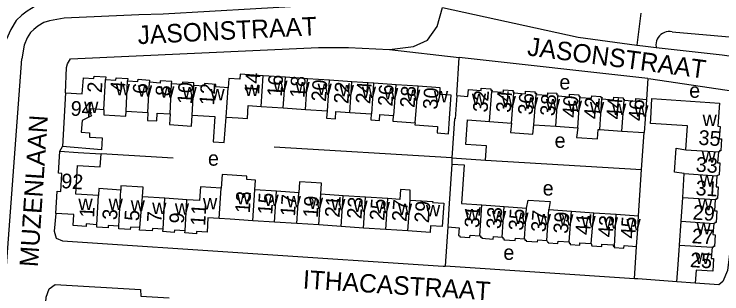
# Model space of a CAD drawing. Extents: x 161773 to 163836, y 384796 to 386521.
# Drawn here: x 162054.9 to 162246.8, y 386283.2 to 386359.1 of the extents above; entities that cross this region are included whole.
import ezdxf

# ---------------------------------------------------------------- set-up
doc = ezdxf.new("R2010")
doc.units = 0
for name, color, linetype in [('BLT_Basislijn', 7, 'Continuous'), ('BLT_Bebouwing', 7, 'Continuous'), ('BLT_Centroide', 7, 'Continuous'), ('BLT_Huisnummer', 7, 'Continuous'), ('BLT_Huisnummer_ tussenligend', 7, 'Continuous'), ('BLT_Huisnummer_reeks', 7, 'Continuous'), ('BLT_Onderverdeling_panden', 7, 'Continuous'), ('BLT_Straatnaam', 7, 'Continuous')]:
    doc.layers.add(name, color=color, linetype=linetype)

msp = doc.modelspace()

# ---------------------------------------------------------------- linework, layer by layer
at = {"layer": 'BLT_Basislijn'}
for p, q in [((162224.77, 386359.37), (162223.74, 386350.72)), ((162088.68, 386358.9), (162068.41, 386357.99)), ((162156.67, 386349.55), (162175.59, 386347.38)), ((162047.33, 386216.15), (162056.95, 386346.98)), ((162174.88, 386337.01), (162175.59, 386347.38)), ((162226.68, 386341.63), (162175.59, 386347.38)), ((162226.68, 386341.63), (162226.35, 386335.99)), ((162225.02, 386316.96), (162225.69, 386326.97)), ((162173.52, 386320.1), (162125.43, 386323.03)), ((162097.96, 386320.09), (162078.46, 386321.21)), ((162173.52, 386320.1), (162173.54, 386318.44)), ((162182.71, 386319.47), (162225.02, 386316.96)), ((162224.19, 386304.39), (162225.02, 386316.96)), ((162172.45, 386301.39), (162171.77, 386290.74)), ((162223.06, 386287.36), (162223.66, 386296.1)), ((162223.06, 386287.36), (162171.77, 386290.74))]:
    msp.add_line(p, q, dxfattribs=at)
for points in [[(162067.88, 386362.97), (162063.25, 386362.18), (162060.78, 386361.41), (162058.37, 386359.89), (162056.99, 386358.79), (162055.44, 386357.35), (162053.96, 386354.94), (162052.75, 386352.1), (162052.68, 386351.64)], [(162132.96, 386361.27), (162095.26, 386359.13), (162088.68, 386358.9)], [(162156.67, 386349.55), (162163.16, 386350.3), (162166.96, 386352.02), (162169.55, 386355.75), (162171.05, 386360.94)], [(162171.05, 386360.94), (162207.82, 386352.89), (162223.74, 386350.72)], [(162068.41, 386357.99), (162064.42, 386357.31), (162062.89, 386356.83), (162061.27, 386355.81), (162060.25, 386354.99), (162059.34, 386354.15), (162058.42, 386352.65), (162057.59, 386350.68), (162056.95, 386346.98)], [(162233.3, 386354.28), (162232.77, 386354.36), (162232.23, 386354.36), (162231.7, 386354.29), (162231.19, 386354.13), (162230.7, 386353.9), (162230.26, 386353.6), (162229.86, 386353.23), (162229.53, 386352.82), (162229.26, 386352.35), (162229.06, 386351.85), (162228.93, 386351.33), (162228.89, 386350.8), (162228.93, 386350.26), (162228.95, 386350.1)], [(162233.3, 386354.28), (162265.36, 386351.49), (162269.14, 386352.49), (162269.74, 386352.29), (162268.92, 386345.92)], [(162068.81, 386337.78), (162069.09, 386344.65), (162069.34, 386345.65), (162070.13, 386346.96), (162137.43, 386350.02), (162145.51, 386350.06), (162156.67, 386349.55)], [(162223.74, 386350.72), (162225.34, 386350.5), (162228.95, 386350.1)], [(162228.95, 386350.1), (162246.84, 386348.11), (162257.79, 386346.51)], [(162226.68, 386341.63), (162227.56, 386341.53), (162250.01, 386338.22), (162251.35, 386337.36), (162252.67, 386335.96), (162253.5, 386333.29), (162253.45, 386331.89), (162248.27, 386289.55), (162247.01, 386286.61), (162245.96, 386285.7), (162239.56, 386286.16)], [(162067.26, 386321.95), (162068.01, 386323.2)], [(162066.15, 386305.08), (162065.72, 386300.28), (162066.31, 386298.33), (162067.96, 386297.64), (162171.21, 386290.78), (162171.77, 386290.74)], [(162234.62, 386286.49), (162224.01, 386287.3), (162223.06, 386287.36)], [(162060.34, 386233.61), (162060.37, 386234.09), (162063.55, 386282.31), (162064.37, 386284.59), (162065.99, 386285.78), (162089.17, 386284.41), (162089.19, 386282.64), (162096.88, 386282.13)]]:
    msp.add_lwpolyline(points, dxfattribs=at)
at = {"layer": 'BLT_Bebouwing'}
for p, q in [((162128.44, 386341.98), (162122.44, 386342.38)), ((162134.43, 386341.57), (162128.44, 386341.98)), ((162079.65, 386341.41), (162079.66, 386341.41)), ((162140.43, 386341.16), (162134.43, 386341.57)), ((162146.43, 386340.75), (162140.43, 386341.16)), ((162152.43, 386340.35), (162146.43, 386340.75)), ((162158.43, 386339.94), (162152.43, 386340.35)), ((162112.89, 386339.12), (162109.55, 386339.35)), ((162164.43, 386339.53), (162158.43, 386339.94)), ((162068.81, 386337.78), (162068.01, 386323.2)), ((162068.81, 386337.78), (162073.36, 386337.47)), ((162085.24, 386332.79), (162091.15, 386332.43)), ((162121.87, 386334.08), (162127.87, 386333.67)), ((162127.87, 386333.67), (162133.87, 386333.27)), ((162133.87, 386333.27), (162139.75, 386332.87)), ((162145.87, 386332.45), (162151.68, 386332.05)), ((162183.79, 386329.97), (162189.77, 386329.54)), ((162195.76, 386329.11), (162201.74, 386328.69)), ((162201.74, 386328.69), (162207.73, 386328.26)), ((162213.72, 386327.83), (162219.7, 386327.4)), ((162219.7, 386327.4), (162225.69, 386326.97)), ((162078.53, 386322.33), (162068.01, 386323.2)), ((162173.52, 386320.1), (162182.71, 386319.47)), ((162236.17, 386309.4), (162236.6, 386315.87)), ((162126.04, 386311.08), (162120.14, 386311.47)), ((162095.7, 386309.17), (162089.72, 386309.57)), ((162132.07, 386310.68), (162126.04, 386311.08)), ((162144.13, 386309.87), (162138.03, 386310.28)), ((162150.16, 386309.47), (162144.13, 386309.87)), ((162156.2, 386309.07), (162150.16, 386309.47)), ((162235.73, 386302.93), (162236.17, 386309.4)), ((162101.69, 386308.77), (162095.7, 386309.17)), ((162181.7, 386307.38), (162187.77, 386306.95)), ((162187.77, 386306.95), (162193.84, 386306.52)), ((162199.91, 386306.1), (162205.98, 386305.67)), ((162205.98, 386305.67), (162212.05, 386305.24)), ((162212.05, 386305.24), (162218.12, 386304.82)), ((162218.12, 386304.82), (162224.19, 386304.39)), ((162125.49, 386302.69), (162119.59, 386303.07)), ((162131.52, 386302.29), (162125.49, 386302.69)), ((162137.48, 386301.93), (162131.52, 386302.29)), ((162143.58, 386301.49), (162137.48, 386301.93)), ((162235.29, 386296.46), (162235.73, 386302.93)), ((162088.91, 386300.52), (162088.95, 386301.2)), ((162149.61, 386301.09), (162143.58, 386301.49)), ((162155.64, 386300.69), (162149.61, 386301.09)), ((162161.67, 386300.29), (162155.64, 386300.69))]:
    msp.add_line(p, q, dxfattribs=at)
for points in [[(162073.36, 386337.47), (162073.65, 386341.86), (162076.53, 386341.67), (162076.58, 386342.29), (162079.7, 386342.08), (162079.65, 386341.41)], [(162122.44, 386342.38), (162116.14, 386342.81), (162116.05, 386341.44), (162113.06, 386341.64), (162112.89, 386339.12)], [(162079.66, 386341.41), (162082.45, 386341.22), (162082.5, 386341.85), (162085.66, 386341.63), (162085.62, 386341)], [(162085.62, 386341), (162088.46, 386340.81), (162088.51, 386341.45), (162091.59, 386341.24), (162091.54, 386340.63)], [(162097.55, 386340.2), (162097.6, 386340.84), (162094.49, 386341.05), (162094.45, 386340.43), (162091.54, 386340.63)], [(162103.59, 386339.76), (162103.64, 386340.45), (162100.49, 386340.67), (162100.45, 386340), (162097.55, 386340.2)], [(162109.55, 386339.35), (162109.6, 386340.06), (162106.49, 386340.27), (162106.44, 386339.57), (162103.59, 386339.76)], [(162173.4, 386337.1), (162170.27, 386337.32), (162170.4, 386339.13), (162164.43, 386339.53)], [(162174.88, 386337.01), (162177.93, 386336.8), (162178.05, 386338.64), (162181.51, 386338.4), (162181.55, 386339.03), (162184.17, 386338.85), (162184.14, 386338.47), (162184.47, 386338.45), (162184.37, 386338.14)], [(162184.37, 386338.14), (162187.53, 386337.92), (162187.58, 386338.61), (162190.15, 386338.43), (162190.12, 386338.05), (162190.4, 386338.04), (162190.38, 386337.75)], [(162190.38, 386337.75), (162193.53, 386337.53), (162193.58, 386338.2), (162196.12, 386338.02), (162196.1, 386337.66), (162196.48, 386337.64), (162196.46, 386337.33)], [(162163.58, 386329.65), (162163.54, 386329.06), (162169.7, 386328.6), (162169.57, 386326.9), (162172.69, 386326.67), (162172.97, 386330.81), (162173.06, 386332.12), (162173.4, 386337.1)], [(162174.88, 386337.01), (162174.54, 386332.02), (162174.45, 386330.71), (162174.25, 386330.72), (162173.52, 386320.1)], [(162196.46, 386337.33), (162199.55, 386337.12), (162199.59, 386337.76), (162202, 386337.64), (162201.97, 386337.28), (162202.34, 386337.25), (162202.33, 386336.93)], [(162202.33, 386336.93), (162205.43, 386336.7), (162205.48, 386337.39), (162207.99, 386337.21), (162207.97, 386336.86), (162208.29, 386336.83), (162208.27, 386336.53)], [(162208.27, 386336.53), (162211.44, 386336.29), (162211.5, 386336.99), (162214.01, 386336.81), (162213.98, 386336.48), (162214.31, 386336.46), (162214.28, 386336.14)], [(162214.28, 386336.14), (162217.42, 386335.91), (162217.47, 386336.61), (162220.04, 386336.43), (162220.01, 386336.07), (162220.29, 386336.05), (162220.3, 386335.74)], [(162220.3, 386335.74), (162223.43, 386335.51), (162223.48, 386336.2), (162226.35, 386335.99)], [(162237.04, 386322.34), (162237.47, 386328.82), (162227.47, 386329.49), (162227.55, 386330.75), (162227.83, 386336.23), (162246.14, 386335), (162245.65, 386328.72), (162246.31, 386328.67), (162246.08, 386325.3), (162246.73, 386325.25), (162246.51, 386322.07), (162246.15, 386322.09), (162246.13, 386321.8), (162245.83, 386321.75)], [(162118.13, 386330.81), (162118.34, 386334.32), (162121.87, 386334.08)], [(162226.35, 386335.99), (162225.96, 386330.64), (162225.69, 386326.97)], [(162075.59, 386333.4), (162075.52, 386332.26), (162075.87, 386331.51), (162073.28, 386330.28), (162073.04, 386327.07), (162075.35, 386326.9), (162075.27, 386325.78), (162078.76, 386325.53), (162078.53, 386322.33)], [(162079.17, 386333.16), (162078.08, 386333.22), (162075.59, 386333.4)], [(162079.17, 386333.16), (162079.16, 386331.77), (162085.13, 386331.41), (162085.24, 386332.79)], [(162091.15, 386332.43), (162091.01, 386330.3), (162093.53, 386330.16), (162093.65, 386332.28), (162097.15, 386332.07)], [(162139.75, 386332.87), (162139.62, 386330.88), (162141.99, 386330.72), (162142.12, 386332.7), (162145.87, 386332.45)], [(162097.15, 386332.07), (162096.96, 386329.18), (162102.99, 386328.77), (162103.19, 386331.71)], [(162103.19, 386331.71), (162109.29, 386331.34), (162108.81, 386324.46), (162111.85, 386324.25), (162112.33, 386331.16)], [(162112.33, 386331.16), (162115.63, 386330.96), (162118.13, 386330.81)], [(162151.68, 386332.05), (162151.57, 386330.42), (162153.94, 386330.26), (162154.05, 386331.89), (162157.69, 386331.65)], [(162157.69, 386331.65), (162157.57, 386330.06), (162163.58, 386329.65)], [(162182.71, 386319.47), (162182.98, 386323.38), (162177.35, 386323.77), (162177.8, 386330.4), (162183.79, 386329.97)], [(162189.77, 386329.54), (162189.51, 386326.99), (162195.54, 386326.58), (162195.76, 386329.11)], [(162207.73, 386328.26), (162207.38, 386325.67), (162213.09, 386325.28), (162213.26, 386327.86), (162213.72, 386327.83)], [(162066.15, 386305.08), (162066.55, 386311.11), (162067.52, 386311.04), (162067.84, 386315.92), (162066.86, 386315.99), (162067.26, 386321.95)], [(162067.26, 386321.95), (162072.25, 386321.62), (162078.46, 386321.21)], [(162077.71, 386309.91), (162071.56, 386310.32), (162072.08, 386318.07), (162078.22, 386317.66), (162078.46, 386321.21)], [(162236.6, 386315.87), (162233.97, 386316.23), (162234.41, 386322.73), (162237.04, 386322.34)], [(162245.83, 386321.75), (162245.63, 386318.82), (162246.26, 386318.78), (162246.04, 386315.52), (162245.43, 386315.28)], [(162173.54, 386318.44), (162172.77, 386306.38), (162172.45, 386301.39)], [(162173.54, 386318.44), (162176.88, 386318.23), (162176.21, 386307.76), (162181.7, 386307.38)], [(162120.14, 386311.47), (162120.31, 386314.07), (162117.94, 386314.23), (162118, 386315.12), (162111.24, 386315.57), (162110.98, 386311.92)], [(162245.43, 386315.28), (162245.23, 386312.3), (162245.82, 386312.26), (162245.61, 386309.08), (162245.3, 386309.1), (162245.29, 386308.85), (162244.97, 386308.81)], [(162138.03, 386310.28), (162138.22, 386313.27), (162135.46, 386313.46), (162132.29, 386313.67), (162132.07, 386310.68)], [(162083.78, 386311.41), (162077.84, 386311.8), (162077.71, 386309.91)], [(162089.72, 386309.57), (162089.83, 386312.16), (162083.81, 386312.57), (162083.78, 386311.41)], [(162110.98, 386311.92), (162105.39, 386312.29), (162105.14, 386308.54), (162101.69, 386308.77)], [(162162.23, 386308.67), (162162.28, 386311.38), (162159.63, 386311.55), (162159.46, 386308.85), (162156.2, 386309.07)], [(162162.23, 386308.67), (162168.37, 386308.26), (162168.35, 386308.04), (162171.41, 386307.84), (162171.3, 386306.48), (162170.93, 386301.49)], [(162193.84, 386306.52), (162194.26, 386308.65), (162200.25, 386308.26), (162199.91, 386306.1)], [(162244.97, 386308.81), (162244.77, 386305.79), (162245.44, 386305.74), (162245.23, 386302.6), (162244.89, 386302.62), (162244.87, 386302.37), (162244.57, 386302.34)], [(162077.31, 386302), (162074.43, 386302.19), (162074.39, 386301.5), (162070.85, 386301.74), (162071.06, 386304.75), (162066.15, 386305.08)], [(162110.43, 386303.69), (162107.44, 386303.89), (162107.18, 386299.97), (162104.34, 386300.16), (162104.3, 386299.54), (162101.17, 386299.75), (162101.21, 386300.34)], [(162119.59, 386303.07), (162113.42, 386303.49), (162110.43, 386303.69)], [(162223.66, 386296.1), (162223.96, 386300.78), (162224.19, 386304.39)], [(162083.28, 386301.57), (162080.41, 386301.76), (162080.37, 386301.13), (162077.26, 386301.34), (162077.31, 386302)], [(162170.93, 386301.49), (162167.82, 386301.7), (162167.7, 386299.89), (162161.67, 386300.29)], [(162244.57, 386302.34), (162244.37, 386299.33), (162245, 386299.29), (162244.78, 386296.09), (162244.44, 386296.11), (162244.42, 386295.84), (162244.12, 386295.86)], [(162088.95, 386301.2), (162086.39, 386301.37), (162086.35, 386300.72), (162083.24, 386300.92), (162083.28, 386301.57)], [(162095.25, 386300.75), (162092.36, 386300.95), (162092.31, 386300.3), (162088.91, 386300.52)], [(162101.21, 386300.34), (162098.34, 386300.53), (162098.3, 386299.9), (162095.21, 386300.11), (162095.25, 386300.75)], [(162172.45, 386301.39), (162175.51, 386301.19), (162175.37, 386299.04), (162175.72, 386299.02), (162175.7, 386298.72), (162178.48, 386298.54), (162178.52, 386299.18), (162181.12, 386299.01)], [(162181.12, 386299.01), (162181.36, 386298.99), (162181.34, 386298.63), (162181.71, 386298.61), (162181.69, 386298.32), (162184.79, 386298.11), (162184.83, 386298.76), (162187.19, 386298.6)], [(162187.19, 386298.6), (162187.4, 386298.59), (162187.38, 386298.22), (162187.71, 386298.2), (162187.7, 386297.9), (162190.77, 386297.69), (162190.82, 386298.36), (162193.26, 386298.2)], [(162193.26, 386298.2), (162193.4, 386298.2), (162193.37, 386297.79), (162193.72, 386297.76), (162193.7, 386297.51), (162196.8, 386297.31), (162196.84, 386297.92), (162199.33, 386297.75)], [(162199.33, 386297.75), (162199.37, 386297.38), (162199.7, 386297.27), (162199.68, 386297.04), (162202.33, 386296.87), (162202.37, 386297.55), (162205.4, 386297.35)], [(162205.4, 386297.35), (162205.41, 386297.03), (162205.69, 386297.01), (162205.67, 386296.62), (162208.23, 386296.46), (162208.28, 386297.12), (162211.38, 386296.9)], [(162211.38, 386296.9), (162211.54, 386296.26), (162214.21, 386296.09), (162214.25, 386296.73), (162217.34, 386296.54), (162217.32, 386296.19), (162217.65, 386296.17)], [(162217.65, 386296.17), (162217.62, 386295.83), (162220.23, 386295.67), (162220.27, 386296.32), (162223.66, 386296.1)], [(162234.62, 386286.49), (162234.86, 386289.99), (162235.19, 386294.98), (162235.29, 386296.46)], [(162244.12, 386295.86), (162243.92, 386292.84), (162244.55, 386292.8), (162244.32, 386289.35), (162239.79, 386289.65), (162239.56, 386286.16)], [(162239.56, 386286.16), (162234.62, 386286.49)]]:
    msp.add_lwpolyline(points, dxfattribs=at)
at = {"layer": 'BLT_Onderverdeling_panden'}
for p, q in [((162121.87, 386334.08), (162122.44, 386342.38)), ((162127.87, 386333.67), (162128.44, 386341.98)), ((162079.17, 386333.16), (162079.66, 386341.41)), ((162085.24, 386332.79), (162085.62, 386341)), ((162091.15, 386332.43), (162091.54, 386340.63)), ((162097.15, 386332.07), (162097.55, 386340.2)), ((162133.87, 386333.27), (162134.43, 386341.57)), ((162145.87, 386332.45), (162146.43, 386340.75)), ((162103.19, 386331.71), (162103.59, 386339.76)), ((162112.33, 386331.16), (162112.89, 386339.12)), ((162163.58, 386329.65), (162164.43, 386339.53)), ((162183.79, 386329.97), (162184.37, 386338.14)), ((162189.77, 386329.54), (162190.38, 386337.75)), ((162195.76, 386329.11), (162196.46, 386337.33)), ((162201.74, 386328.69), (162202.33, 386336.93)), ((162207.73, 386328.26), (162208.27, 386336.53)), ((162213.72, 386327.83), (162214.28, 386336.14)), ((162219.7, 386327.4), (162220.3, 386335.74)), ((162237.04, 386322.34), (162245.83, 386321.75)), ((162236.6, 386315.87), (162245.43, 386315.28)), ((162083.28, 386301.57), (162083.78, 386311.41)), ((162110.43, 386303.69), (162110.98, 386311.92)), ((162119.59, 386303.07), (162120.14, 386311.47)), ((162077.31, 386302), (162077.71, 386309.91)), ((162088.95, 386301.2), (162089.72, 386309.57)), ((162125.49, 386302.69), (162126.04, 386311.08)), ((162131.52, 386302.29), (162132.07, 386310.68)), ((162137.48, 386301.93), (162138.03, 386310.28)), ((162143.58, 386301.49), (162144.13, 386309.87)), ((162149.61, 386301.09), (162150.16, 386309.47)), ((162236.17, 386309.4), (162244.97, 386308.81)), ((162095.25, 386300.75), (162095.7, 386309.17)), ((162101.21, 386300.34), (162101.69, 386308.77)), ((162155.64, 386300.69), (162156.2, 386309.07)), ((162161.67, 386300.29), (162162.23, 386308.67)), ((162181.12, 386299.01), (162181.7, 386307.38)), ((162187.19, 386298.6), (162187.77, 386306.95)), ((162193.26, 386298.2), (162193.84, 386306.52)), ((162199.33, 386297.75), (162199.91, 386306.1)), ((162205.4, 386297.35), (162205.98, 386305.67)), ((162211.38, 386296.9), (162212.05, 386305.24)), ((162217.65, 386296.17), (162218.12, 386304.82)), ((162235.73, 386302.93), (162244.57, 386302.34)), ((162235.29, 386296.46), (162244.12, 386295.86))]:
    msp.add_line(p, q, dxfattribs=at)
for points in [[(162139.75, 386332.87), (162139.87, 386332.86), (162140.43, 386341.16)], [(162151.68, 386332.05), (162151.87, 386332.04), (162152.43, 386340.35)], [(162157.69, 386331.65), (162157.87, 386331.63), (162158.43, 386339.94)]]:
    msp.add_lwpolyline(points, dxfattribs=at)

# ---------------------------------------------------------------- texts
at = {"layer": 'BLT_Centroide'}
for s, p in [('w', (162082.41, 386337.09)), ('w', (162125.16, 386338.02)), ('w', (162131.16, 386337.61)), ('w', (162137.16, 386337.2)), ('e', (162202.73, 386338.69)), ('w', (162088.42, 386336.7)), ('w', (162094.47, 386336.42)), ('w', (162100.52, 386336.27)), ('w', (162108.09, 386335.72)), ('w', (162117.4, 386336.88)), ('w', (162143.16, 386336.8)), ('w', (162149.16, 386336.39)), ('w', (162155.16, 386335.98)), ('w', (162161.16, 386335.58)), ('w', (162168.7, 386335.16)), ('e', (162237.93, 386336.42)), ('w', (162179, 386334.44)), ('w', (162187.09, 386333.86)), ('w', (162193.12, 386333.44)), ('w', (162073.86, 386332.28)), ('w', (162199.05, 386333.02)), ('w', (162205.02, 386332.58)), ('w', (162211.02, 386332.17)), ('w', (162217, 386331.77)), ('w', (162223.03, 386331.34)), ('w', (162241.56, 386328.75)), ('e', (162201.43, 386322.85)), ('e', (162107.44, 386318)), ('w', (162241.31, 386318.81)), ('w', (162240.8, 386312.34)), ('e', (162198.2, 386309.92)), ('w', (162115.22, 386307.5)), ('w', (162122.75, 386307.08)), ('w', (162128.78, 386306.69)), ('w', (162134.81, 386306.28)), ('w', (162072.3, 386305.95)), ('w', (162080.5, 386305.97)), ('w', (162086.48, 386305.58)), ('w', (162092.31, 386304.86)), ('w', (162098.45, 386304.75)), ('w', (162106.08, 386306.14)), ('w', (162140.84, 386305.89)), ('w', (162146.88, 386305.48)), ('w', (162152.91, 386305.08)), ('w', (162158.94, 386304.67)), ('w', (162240.34, 386305.88)), ('w', (162166.54, 386304.28)), ('w', (162177.08, 386303.16)), ('w', (162184.44, 386302.66)), ('w', (162190.52, 386302.23)), ('w', (162196.59, 386301.83)), ('w', (162202.66, 386301.72)), ('w', (162208.72, 386301.28)), ('w', (162214.75, 386300.88)), ('w', (162220.91, 386300.45)), ('w', (162239.93, 386299.38)), ('e', (162187.54, 386292.47)), ('w', (162239.58, 386291.34))]:
    msp.add_text(s, height=4, dxfattribs=at).set_placement(p)
at = {"layer": 'BLT_Huisnummer'}
for s, rotation, p in [('14', 86.1122, (162121.29, 386337.2)), ('18', 86.1122, (162133.59, 386336.31)), ('6', 86.5466, (162091, 386337.34)), ('12', 86.1126, (162109.08, 386334.28)), ('22', 85.9104, (162145.51, 386334.68)), ('26', 86.1122, (162157.46, 386334.01)), ('30', 86.0891, (162169.65, 386333.14)), ('32', 85.9079, (162183.24, 386332.38)), ('36', 85.9119, (162195.45, 386331.68)), ('40', 85.908, (162207.47, 386330.93)), ('46', 86.1463, (162225.42, 386330)), ('35', 356.1418, (162240.35, 386323.7)), ('13', 86.2072, (162118.77, 386305.03)), ('17', 86.2118, (162131.03, 386304.17)), ('21', 86.2068, (162143.09, 386303.85)), ('25', 85.6531, (162155.23, 386303.01)), ('29', 85.9827, (162167.36, 386302.38)), ('5', 86.1918, (162088.74, 386302.91)), ('11', 86.1886, (162106.65, 386301.58)), ('31', 85.9825, (162180.95, 386301.04)), ('35', 85.9827, (162192.91, 386300.31)), ('29', 356.142, (162238.8, 386303.41)), ('39', 85.9825, (162205.05, 386299.46)), ('45', 86.3444, (162223.27, 386298.15)), ('25', 356.1417, (162238.06, 386290.52))]:
    msp.add_text(s, height=4, rotation=rotation, dxfattribs=at).set_placement(p)
at = {"layer": 'BLT_Huisnummer_ tussenligend'}
for s, rotation, p in [('16', 86.1122, (162127.46, 386336.63)), ('4', 86.5452, (162084.9, 386337.89)), ('10', 86.1126, (162103.07, 386334.59)), ('20', 86.1122, (162139.42, 386335.28)), ('24', 85.9104, (162151.44, 386334.67)), ('8', 86.5466, (162097.18, 386336.78)), ('28', 86.1122, (162163.47, 386333.61)), ('34', 85.9079, (162189.5, 386332.29)), ('38', 85.9119, (162201.46, 386331.36)), ('42', 85.908, (162213.32, 386330.54)), ('44', 85.908, (162219.41, 386330.45)), ('33', 356.142, (162239.62, 386316.41)), ('31', 356.142, (162239.58, 386310.04)), ('15', 86.2072, (162124.86, 386304.63)), ('19', 86.2118, (162137.21, 386303.78)), ('23', 86.2068, (162149.07, 386303.48)), ('27', 85.6531, (162161.25, 386302.75)), ('3', 86.1898, (162082.75, 386303.17)), ('33', 85.9825, (162186.86, 386300.75)), ('37', 85.9827, (162199, 386299.89)), ('7', 86.1918, (162094.83, 386302.49)), ('9', 86.1886, (162100.9, 386302.21)), ('41', 85.9825, (162211.02, 386299.1)), ('43', 85.9825, (162217.17, 386298.49)), ('27', 356.1417, (162238.53, 386297.02))]:
    msp.add_text(s, height=4, rotation=rotation, dxfattribs=at).set_placement(p)
at = {"layer": 'BLT_Huisnummer_reeks'}
for s, rotation, p in [('2', 86.5456, (162078.65, 386337.67)), ('94', 356.1088, (162070.08, 386331.62)), ('92', 356.1939, (162067.53, 386311.94)), ('1', 87.053, (162076.55, 386303.82))]:
    msp.add_text(s, height=4, rotation=rotation, dxfattribs=at).set_placement(p)
at = {"layer": 'BLT_Straatnaam'}
for s, rotation, p in [('JASONSTRAAT', 2.92, (162088.47, 386350.94)), ('JASONSTRAAT', 352.5385, (162193.84, 386347.94)), ('MUZENLAAN', 86.2215, (162061.32, 386290.41)), ('ITHACASTRAAT', 356.3298, (162133.06, 386284.73))]:
    msp.add_text(s, height=5, rotation=rotation, dxfattribs=at).set_placement(p)

doc.saveas('drawing.dxf')
